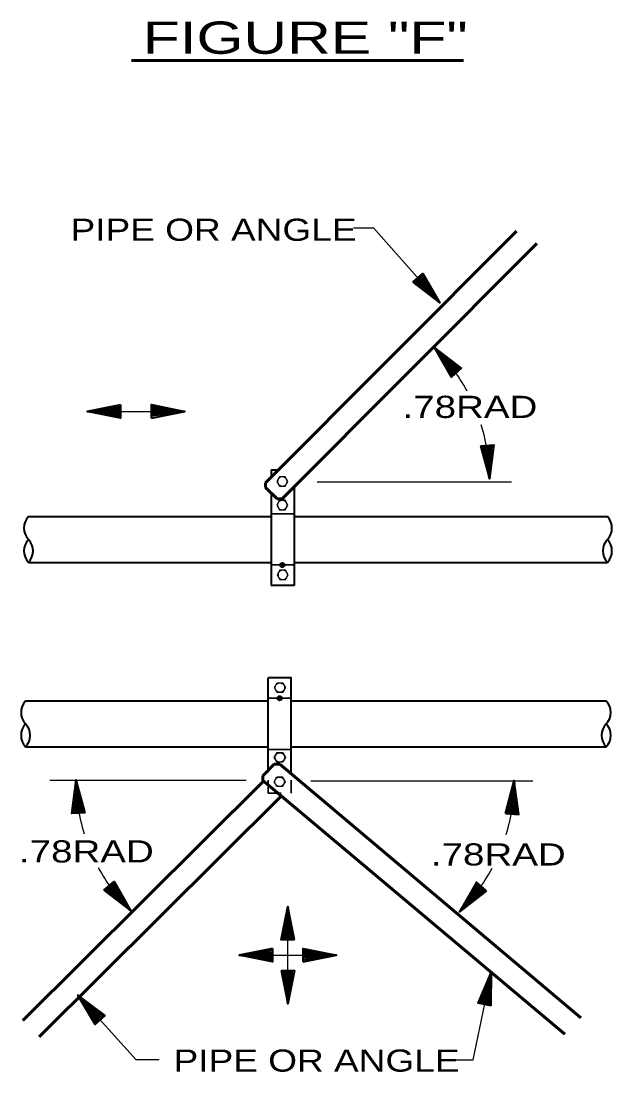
# Model space of a CAD drawing. Extents: x 55 to 190, y 198 to 264.
# Drawn here: x 79.41 to 86.18, y 236.14 to 248.19 of the extents above; entities that cross this region are included whole.
import ezdxf
from ezdxf.enums import TextEntityAlignment as Align

# ---------------------------------------------------------------- set-up
doc = ezdxf.new("R2010")
doc.units = 0
doc.header["$LTSCALE"] = 0.1
doc.header["$PDMODE"] = 32
doc.header["$PDSIZE"] = 0.05
doc.linetypes.add('SHORT_DASHED', pattern=[2.7, 1.5, -1.2])
doc.layers.add('2', color=7, linetype='Continuous', lineweight=40)

msp = doc.modelspace()

# ---------------------------------------------------------------- linework, layer by layer
at = {"layer": '2', "lineweight": 60}
for p, q in [((80.6718, 247.7391), (84.48, 247.7391)), ((82.2109, 242.8975), (85.0859, 245.7806)), ((82.3987, 242.7112), (85.3205, 245.6415)), ((82.2109, 242.8972), (82.2109, 242.8427)), ((82.2109, 242.8427), (82.3429, 242.7112)), ((82.3429, 242.7112), (82.399, 242.7112)), ((82.1784, 239.537), (82.3104, 239.6685)), ((82.3104, 239.6685), (82.3733, 239.6685)), ((82.3733, 239.6685), (85.827, 236.761)), ((82.1868, 239.4756), (79.4264, 236.7303)), ((82.1784, 239.4825), (82.1784, 239.537)), ((82.1784, 239.4825), (85.6415, 236.5734)), ((82.39, 239.3047), (79.6145, 236.544))]:
    msp.add_line(p, q, dxfattribs=at)
at = {"layer": '2'}
for p, q in [((84.2098, 244.9618), (83.9698, 245.2599)), ((84.2098, 244.9618), (83.9976, 245.2848)), ((84.2098, 244.9618), (83.9132, 245.2099)), ((84.2098, 244.9618), (83.9288, 245.2245)), ((84.2098, 244.9618), (83.9421, 245.2353)), ((83.9553, 245.2475), (84.2098, 244.9618)), ((84.3998, 244.1595), (84.1469, 244.4466)), ((84.1469, 244.4466), (84.426, 244.182)), ((84.1469, 244.4466), (84.3572, 244.1225)), ((84.1469, 244.4466), (84.385, 244.1468)), ((84.1469, 244.4466), (84.413, 244.1714)), ((84.1469, 244.4466), (84.4419, 244.1966)), ((80.1654, 243.7158), (80.5477, 243.7727)), ((80.1654, 243.7158), (80.5482, 243.7513)), ((80.1654, 243.7158), (80.5477, 243.7341)), ((80.548, 243.7164), (80.1654, 243.7158)), ((80.1654, 243.7158), (80.5477, 243.6597)), ((80.1654, 243.7158), (80.5477, 243.6971)), ((81.2827, 243.7158), (80.8999, 243.6804)), ((80.9001, 243.7153), (81.2827, 243.7158)), ((81.2827, 243.7158), (80.9004, 243.7719)), ((81.2827, 243.7158), (80.9004, 243.7346)), ((81.2827, 243.7158), (80.9004, 243.6976)), ((81.2827, 243.7158), (80.9004, 243.659)), ((84.7763, 242.9435), (84.8054, 243.3288)), ((84.7763, 242.9435), (84.693, 243.3211)), ((84.7763, 242.9435), (84.7141, 243.3229)), ((84.7763, 242.9435), (84.7311, 243.3237)), ((84.749, 243.325), (84.7763, 242.9435)), ((84.7763, 242.9435), (84.7681, 243.3264)), ((82.2733, 243.0438), (82.2733, 242.9602)), ((82.2733, 243.0438), (82.3606, 243.0438)), ((82.5379, 242.8509), (82.5379, 241.7195)), ((82.2733, 242.7805), (82.2733, 241.7195)), ((79.4912, 242.5117), (82.2733, 242.5117)), ((82.5379, 242.5117), (86.1296, 242.5114)), ((79.4912, 241.9826), (82.2733, 241.9826)), ((82.5379, 241.9826), (86.1296, 241.9823)), ((82.5379, 241.7195), (82.2733, 241.7195)), ((82.2408, 239.5992), (82.2408, 240.6601)), ((82.5056, 240.6601), (82.2408, 240.6601)), ((82.5054, 239.5574), (82.5054, 240.6601)), ((79.4587, 240.3972), (82.2408, 240.3972)), ((82.5054, 240.3972), (86.1164, 240.3972)), ((79.4587, 239.868), (82.2408, 239.868)), ((82.5054, 239.868), (86.1164, 239.868)), ((80.0368, 239.4894), (80.0077, 239.1041)), ((80.0641, 239.1079), (80.0368, 239.4894)), ((80.0368, 239.4894), (80.099, 239.11)), ((80.0368, 239.4894), (80.045, 239.1065)), ((80.0368, 239.4894), (80.0821, 239.1092)), ((80.0368, 239.4894), (80.1202, 239.1118)), ((85.0626, 239.4814), (84.9792, 239.1039)), ((85.0626, 239.4814), (85.0004, 239.102)), ((85.0626, 239.4814), (85.0173, 239.1012)), ((85.0353, 239.0999), (85.0626, 239.4814)), ((85.0626, 239.4814), (85.0544, 239.0986)), ((85.0626, 239.4814), (85.0917, 239.0962)), ((80.4133, 238.2734), (80.6663, 237.9863)), ((80.6663, 237.9863), (80.4281, 238.2861)), ((80.6663, 237.9863), (80.4559, 238.3104)), ((84.4331, 237.9783), (84.6435, 238.3025)), ((84.4331, 237.9783), (84.6713, 238.2781)), ((80.6663, 237.9863), (80.3712, 238.2363)), ((80.6663, 237.9863), (80.3871, 238.2509)), ((80.6663, 237.9863), (80.4001, 238.2614)), ((84.6861, 238.2654), (84.4331, 237.9783)), ((84.4331, 237.9783), (84.6993, 238.2535)), ((84.4331, 237.9783), (84.7123, 238.2429)), ((84.4331, 237.9783), (84.7281, 238.2284)), ((82.4644, 238.0376), (82.4083, 237.6553)), ((82.4644, 238.0376), (82.4456, 237.6553)), ((82.4649, 237.655), (82.4644, 238.0376)), ((82.4644, 238.0376), (82.4998, 237.6547)), ((82.4644, 238.0376), (82.4826, 237.6553)), ((82.4644, 238.0376), (82.5212, 237.6553)), ((81.9058, 237.4788), (82.2882, 237.5357)), ((81.9058, 237.4788), (82.2887, 237.5143)), ((81.9058, 237.4788), (82.2882, 237.4971)), ((82.2884, 237.4793), (81.9058, 237.4788)), ((81.9058, 237.4788), (82.2882, 237.4227)), ((81.9058, 237.4788), (82.2882, 237.46)), ((83.0232, 237.4788), (82.6403, 237.4434)), ((82.6406, 237.4783), (83.0232, 237.4788)), ((83.0232, 237.4788), (82.6408, 237.5349)), ((83.0232, 237.4788), (82.6408, 237.4976)), ((83.0232, 237.4788), (82.6408, 237.4605)), ((83.0232, 237.4788), (82.6408, 237.4219)), ((82.4644, 236.9203), (82.4075, 237.3026)), ((82.4644, 236.9203), (82.4289, 237.3031)), ((82.4644, 236.9203), (82.4461, 237.3026)), ((82.4638, 237.3029), (82.4644, 236.9203)), ((82.4644, 236.9203), (82.5204, 237.3026)), ((82.4644, 236.9203), (82.4832, 237.3026)), ((84.8001, 237.287), (84.6676, 236.924)), ((84.8001, 237.287), (84.7043, 236.9163)), ((84.7228, 236.9121), (84.8001, 237.287)), ((84.8001, 237.287), (84.7406, 236.9089)), ((84.8001, 237.287), (84.757, 236.9049)), ((84.8001, 237.287), (84.7781, 236.901)), ((80.3144, 236.7359), (80.0582, 237.0203)), ((80.0582, 237.0203), (80.3403, 236.7589)), ((80.0582, 237.0203), (80.272, 236.6983)), ((80.0582, 237.0203), (80.2998, 236.7231)), ((80.0582, 237.0203), (80.3273, 236.748)), ((80.0582, 237.0203), (80.3559, 236.7737))]:
    msp.add_line(p, q, dxfattribs=at)
at = {"layer": '2', "lineweight": 25}
for p, q in [((80.1654, 243.7158), (81.2827, 243.7158)), ((82.8012, 242.9091), (85.0287, 242.9091)), ((81.9884, 239.4836), (79.7344, 239.4836)), ((82.7287, 239.478), (85.2764, 239.478)), ((82.4644, 236.9203), (82.4644, 238.0376)), ((81.9058, 237.4788), (83.0232, 237.4788))]:
    msp.add_line(p, q, dxfattribs=at)
at = {"layer": '2', "lineweight": 35}
for p, q in [((82.2736, 242.5405), (82.5387, 242.5405)), ((82.2736, 241.954), (82.5387, 241.954)), ((82.2411, 240.4257), (82.5062, 240.4257)), ((82.2411, 239.8391), (82.5062, 239.8391))]:
    msp.add_line(p, q, dxfattribs=at)
at = {"layer": '2', "linetype": 'SHORT_DASHED', "lineweight": 35}
for p, q in [((82.2408, 239.3359), (82.2408, 239.5992)), ((82.5054, 239.3359), (82.5054, 239.5574)), ((82.2408, 239.3359), (82.5054, 239.3359))]:
    msp.add_line(p, q, dxfattribs=at)
at = {"layer": '2', "lineweight": 25}
for points in [[(83.2195, 245.8187), (83.4481, 245.8187), (84.2098, 244.9618)], [(82.4572, 242.9118), (82.4569, 242.9152), (82.4567, 242.9186), (82.4562, 242.9218), (82.4554, 242.9253), (82.4546, 242.9284), (82.4533, 242.9316), (82.4519, 242.9348), (82.4503, 242.938), (82.4488, 242.9409), (82.4469, 242.9438), (82.4448, 242.9464), (82.4424, 242.9491), (82.44, 242.9515), (82.4374, 242.9536), (82.4347, 242.9557), (82.4318, 242.9575), (82.4289, 242.9594), (82.426, 242.961), (82.4228, 242.9623), (82.4196, 242.9633), (82.4162, 242.9644), (82.413, 242.9652), (82.4096, 242.9657), (82.4062, 242.966), (82.4027, 242.966), (82.3993, 242.966), (82.3958, 242.9657), (82.3927, 242.9652), (82.3892, 242.9644), (82.386, 242.9633), (82.3829, 242.9623), (82.3797, 242.961), (82.3765, 242.9594), (82.3736, 242.9575), (82.3707, 242.9557), (82.3681, 242.9536), (82.3654, 242.9515), (82.363, 242.9491), (82.3609, 242.9464), (82.3588, 242.9438), (82.3569, 242.9409), (82.3551, 242.938), (82.3535, 242.9348), (82.3522, 242.9316), (82.3511, 242.9284), (82.3501, 242.9253), (82.3493, 242.9218), (82.3487, 242.9186), (82.3485, 242.9152), (82.3485, 242.9118), (82.3485, 242.9083), (82.3487, 242.9049), (82.3493, 242.9014), (82.3501, 242.8983), (82.3511, 242.8948), (82.3522, 242.8917), (82.3535, 242.8885), (82.3551, 242.8856), (82.3569, 242.8827), (82.3588, 242.8798), (82.3609, 242.8771), (82.363, 242.8745), (82.3654, 242.8721), (82.3681, 242.8697), (82.3707, 242.8676), (82.3736, 242.8657), (82.3765, 242.8641), (82.3797, 242.8625), (82.3829, 242.8612), (82.386, 242.8599), (82.3892, 242.8591), (82.3927, 242.8583), (82.3958, 242.8578), (82.3993, 242.8575), (82.4027, 242.8573), (82.4062, 242.8575), (82.4096, 242.8578), (82.413, 242.8583), (82.4162, 242.8591), (82.4196, 242.8599), (82.4228, 242.8612), (82.426, 242.8625), (82.4289, 242.8641), (82.4318, 242.8657), (82.4347, 242.8676), (82.4374, 242.8697), (82.44, 242.8721), (82.4424, 242.8745), (82.4448, 242.8771), (82.4469, 242.8798), (82.4488, 242.8827), (82.4503, 242.8856), (82.4519, 242.8885), (82.4533, 242.8917), (82.4546, 242.8948), (82.4554, 242.8983), (82.4562, 242.9014), (82.4567, 242.9049)], [(82.4564, 242.6406), (82.4564, 242.644), (82.4559, 242.6474), (82.4554, 242.6509), (82.4548, 242.6541), (82.4538, 242.6575), (82.4527, 242.6607), (82.4514, 242.6639), (82.4498, 242.6668), (82.448, 242.6697), (82.4461, 242.6726), (82.444, 242.6752), (82.4416, 242.6779), (82.4392, 242.6803), (82.4368, 242.6824), (82.4339, 242.6845), (82.4313, 242.6866), (82.4284, 242.6882), (82.4252, 242.6898), (82.422, 242.6911), (82.4189, 242.6924), (82.4157, 242.6932), (82.4122, 242.694), (82.4088, 242.6945), (82.4054, 242.6948), (82.4022, 242.6951), (82.3987, 242.6948), (82.3953, 242.6945), (82.3919, 242.694), (82.3884, 242.6932), (82.3853, 242.6924), (82.3821, 242.6911), (82.3789, 242.6898), (82.3757, 242.6882), (82.3728, 242.6866), (82.3702, 242.6845), (82.3673, 242.6824), (82.3649, 242.6803), (82.3625, 242.6779), (82.3601, 242.6752), (82.358, 242.6726), (82.3562, 242.6697), (82.3543, 242.6668), (82.3527, 242.6639), (82.3514, 242.6607), (82.3503, 242.6575), (82.3493, 242.6541), (82.3487, 242.6509), (82.3482, 242.6474), (82.3477, 242.644), (82.3477, 242.6406), (82.3477, 242.6371), (82.3482, 242.6337), (82.3487, 242.6303), (82.3493, 242.6271), (82.3503, 242.6236), (82.3514, 242.6205), (82.3527, 242.6173), (82.3543, 242.6144), (82.3562, 242.6115), (82.358, 242.6086), (82.3601, 242.6059), (82.3625, 242.6033), (82.3649, 242.6009), (82.3673, 242.5988), (82.3702, 242.5966), (82.3728, 242.5945), (82.3757, 242.5929), (82.3789, 242.5914), (82.3821, 242.59), (82.3853, 242.5887), (82.3884, 242.5879), (82.3919, 242.5871), (82.3953, 242.5866), (82.3987, 242.5863), (82.4022, 242.5861), (82.4054, 242.5863), (82.4088, 242.5866), (82.4122, 242.5871), (82.4157, 242.5879), (82.4189, 242.5887), (82.422, 242.59), (82.4252, 242.5914), (82.4284, 242.5929), (82.4313, 242.5945), (82.4339, 242.5966), (82.4368, 242.5988), (82.4392, 242.6009), (82.4416, 242.6033), (82.444, 242.6059), (82.4461, 242.6086), (82.448, 242.6115), (82.4498, 242.6144), (82.4514, 242.6173), (82.4527, 242.6205), (82.4538, 242.6236), (82.4548, 242.6271), (82.4554, 242.6303), (82.4559, 242.6337)], [(82.4615, 241.8407), (82.4615, 241.8442), (82.4609, 241.8476), (82.4604, 241.8511), (82.4599, 241.8545), (82.4588, 241.8577), (82.4578, 241.8608), (82.4564, 241.864), (82.4548, 241.8669), (82.453, 241.8701), (82.4511, 241.8727), (82.449, 241.8754), (82.4466, 241.878), (82.4443, 241.8804), (82.4419, 241.8828), (82.439, 241.8849), (82.4363, 241.8868), (82.4334, 241.8886), (82.4302, 241.8899), (82.4271, 241.8915), (82.4239, 241.8926), (82.4207, 241.8936), (82.4173, 241.8942), (82.4138, 241.8947), (82.4104, 241.8952), (82.407, 241.8952), (82.4038, 241.8952), (82.4003, 241.8947), (82.3969, 241.8942), (82.3935, 241.8936), (82.3903, 241.8926), (82.3871, 241.8915), (82.3839, 241.8899), (82.3808, 241.8886), (82.3778, 241.8868), (82.3752, 241.8849), (82.3723, 241.8828), (82.3699, 241.8804), (82.3675, 241.878), (82.3651, 241.8754), (82.363, 241.8727), (82.3612, 241.8701), (82.3593, 241.8669), (82.3577, 241.864), (82.3564, 241.8608), (82.3553, 241.8577), (82.3543, 241.8545), (82.3538, 241.8511), (82.3532, 241.8476), (82.3527, 241.8442), (82.3527, 241.8407), (82.3527, 241.8376), (82.3532, 241.8341), (82.3538, 241.8307), (82.3543, 241.8272), (82.3553, 241.8241), (82.3564, 241.8209), (82.3577, 241.8177), (82.3593, 241.8145), (82.3612, 241.8116), (82.363, 241.809), (82.3651, 241.8061), (82.3675, 241.8037), (82.3699, 241.8013), (82.3723, 241.7989), (82.3752, 241.7968), (82.3778, 241.795), (82.3808, 241.7931), (82.3839, 241.7915), (82.3871, 241.7902), (82.3903, 241.7891), (82.3935, 241.7881), (82.3969, 241.7873), (82.4003, 241.7868), (82.4038, 241.7865), (82.407, 241.7865), (82.4104, 241.7865), (82.4138, 241.7868), (82.4173, 241.7873), (82.4207, 241.7881), (82.4239, 241.7891), (82.4271, 241.7902), (82.4302, 241.7915), (82.4334, 241.7931), (82.4363, 241.795), (82.439, 241.7968), (82.4419, 241.7989), (82.4443, 241.8013), (82.4466, 241.8037), (82.449, 241.8061), (82.4511, 241.809), (82.453, 241.8116), (82.4548, 241.8145), (82.4564, 241.8177), (82.4578, 241.8209), (82.4588, 241.8241), (82.4599, 241.8272), (82.4604, 241.8307), (82.4609, 241.8341)], [(82.4289, 240.5475), (82.4289, 240.544), (82.4286, 240.5406), (82.4281, 240.5371), (82.4273, 240.534), (82.4263, 240.5305), (82.4252, 240.5273), (82.4239, 240.5242), (82.4223, 240.5212), (82.4204, 240.5183), (82.4186, 240.5154), (82.4165, 240.5128), (82.4144, 240.5101), (82.412, 240.5078), (82.4093, 240.5054), (82.4067, 240.5035), (82.4038, 240.5014), (82.4009, 240.4998), (82.3977, 240.4982), (82.3945, 240.4969), (82.3913, 240.4956), (82.3882, 240.4948), (82.3847, 240.494), (82.3816, 240.4935), (82.3781, 240.4932), (82.3747, 240.4929), (82.3712, 240.4932), (82.3678, 240.4935), (82.3643, 240.494), (82.3612, 240.4948), (82.3577, 240.4956), (82.3546, 240.4969), (82.3514, 240.4982), (82.3485, 240.4998), (82.3456, 240.5014), (82.3427, 240.5035), (82.34, 240.5054), (82.3374, 240.5078), (82.335, 240.5101), (82.3326, 240.5128), (82.3305, 240.5154), (82.3286, 240.5183), (82.327, 240.5212), (82.3255, 240.5242), (82.3241, 240.5273), (82.3228, 240.5305), (82.322, 240.534), (82.3212, 240.5371), (82.3207, 240.5406), (82.3204, 240.544), (82.3202, 240.5475), (82.3204, 240.5509), (82.3207, 240.5543), (82.3212, 240.5575), (82.322, 240.5609), (82.3228, 240.5641), (82.3241, 240.5675), (82.3255, 240.5705), (82.327, 240.5736), (82.3286, 240.5765), (82.3305, 240.5795), (82.3326, 240.5821), (82.335, 240.5847), (82.3374, 240.5871), (82.34, 240.5893), (82.3427, 240.5914), (82.3456, 240.5932), (82.3485, 240.5951), (82.3514, 240.5967), (82.3546, 240.598), (82.3577, 240.599), (82.3612, 240.6001), (82.3643, 240.6009), (82.3678, 240.6014), (82.3712, 240.6017), (82.3747, 240.6017), (82.3781, 240.6017), (82.3816, 240.6014), (82.3847, 240.6009), (82.3882, 240.6001), (82.3913, 240.599), (82.3945, 240.598), (82.3977, 240.5967), (82.4009, 240.5951), (82.4038, 240.5932), (82.4067, 240.5914), (82.4093, 240.5893), (82.412, 240.5871), (82.4144, 240.5847), (82.4165, 240.5821), (82.4186, 240.5795), (82.4204, 240.5765), (82.4223, 240.5736), (82.4239, 240.5705), (82.4252, 240.5675), (82.4263, 240.5641), (82.4273, 240.5609), (82.4281, 240.5575), (82.4286, 240.5543)], [(82.4281, 239.7474), (82.4281, 239.7439), (82.4279, 239.7407), (82.4273, 239.7373), (82.4265, 239.7339), (82.4255, 239.7307), (82.4244, 239.7275), (82.4231, 239.7243), (82.4215, 239.7212), (82.4196, 239.7182), (82.4178, 239.7153), (82.4157, 239.7127), (82.4136, 239.7103), (82.4112, 239.7077), (82.4085, 239.7055), (82.4059, 239.7034), (82.403, 239.7016), (82.4001, 239.6997), (82.3969, 239.6981), (82.3937, 239.6968), (82.3905, 239.6958), (82.3874, 239.6947), (82.3839, 239.6939), (82.3808, 239.6934), (82.3773, 239.6931), (82.3739, 239.6931), (82.3704, 239.6931), (82.367, 239.6934), (82.3636, 239.6939), (82.3604, 239.6947), (82.3569, 239.6958), (82.3538, 239.6968), (82.3506, 239.6981), (82.3477, 239.6997), (82.3448, 239.7016), (82.3419, 239.7034), (82.3392, 239.7055), (82.3366, 239.7077), (82.3342, 239.7103), (82.3318, 239.7127), (82.3297, 239.7153), (82.3278, 239.7182), (82.3263, 239.7212), (82.3247, 239.7243), (82.3233, 239.7275), (82.322, 239.7307), (82.3212, 239.7339), (82.3204, 239.7373), (82.3199, 239.7407), (82.3196, 239.7439), (82.3194, 239.7474), (82.3196, 239.7508), (82.3199, 239.7542), (82.3204, 239.7577), (82.3212, 239.7608), (82.322, 239.7643), (82.3233, 239.7675), (82.3247, 239.7706), (82.3263, 239.7735), (82.3278, 239.7765), (82.3297, 239.7794), (82.3318, 239.782), (82.3342, 239.7847), (82.3366, 239.787), (82.3392, 239.7894), (82.3419, 239.7915), (82.3448, 239.7934), (82.3477, 239.795), (82.3506, 239.7966), (82.3538, 239.7979), (82.3569, 239.7992), (82.3604, 239.8), (82.3636, 239.8008), (82.367, 239.8013), (82.3704, 239.8018), (82.3739, 239.8018), (82.3773, 239.8018), (82.3808, 239.8013), (82.3839, 239.8008), (82.3874, 239.8), (82.3905, 239.7992), (82.3937, 239.7979), (82.3969, 239.7966), (82.4001, 239.795), (82.403, 239.7934), (82.4059, 239.7915), (82.4085, 239.7894), (82.4112, 239.787), (82.4136, 239.7847), (82.4157, 239.782), (82.4178, 239.7794), (82.4196, 239.7765), (82.4215, 239.7735), (82.4231, 239.7706), (82.4244, 239.7675), (82.4255, 239.7643), (82.4265, 239.7608), (82.4273, 239.7577), (82.4279, 239.7542)], [(82.4247, 239.4682), (82.4247, 239.4648), (82.4241, 239.4613), (82.4236, 239.4579), (82.4231, 239.4545), (82.422, 239.4513), (82.421, 239.4481), (82.4196, 239.4449), (82.4181, 239.4417), (82.4162, 239.4388), (82.4144, 239.4362), (82.4122, 239.4333), (82.4099, 239.4309), (82.4075, 239.4285), (82.4051, 239.4261), (82.4022, 239.424), (82.3995, 239.4222), (82.3966, 239.4203), (82.3935, 239.4187), (82.3903, 239.4174), (82.3871, 239.4164), (82.3839, 239.4153), (82.3805, 239.4148), (82.3771, 239.4142), (82.3736, 239.4137), (82.3704, 239.4137), (82.367, 239.4137), (82.3636, 239.4142), (82.3601, 239.4148), (82.3567, 239.4153), (82.3535, 239.4164), (82.3503, 239.4174), (82.3472, 239.4187), (82.344, 239.4203), (82.3411, 239.4222), (82.3384, 239.424), (82.3355, 239.4261), (82.3331, 239.4285), (82.3308, 239.4309), (82.3284, 239.4333), (82.3263, 239.4362), (82.3244, 239.4388), (82.3225, 239.4417), (82.321, 239.4449), (82.3196, 239.4481), (82.3186, 239.4513), (82.3175, 239.4545), (82.317, 239.4579), (82.3165, 239.4613), (82.3159, 239.4648), (82.3159, 239.4682), (82.3159, 239.4714), (82.3165, 239.4748), (82.317, 239.4783), (82.3175, 239.4817), (82.3186, 239.4849), (82.3196, 239.488), (82.321, 239.4912), (82.3225, 239.4944), (82.3244, 239.4973), (82.3263, 239.5), (82.3284, 239.5029), (82.3308, 239.5053), (82.3331, 239.5076), (82.3355, 239.51), (82.3384, 239.5121), (82.3411, 239.514), (82.344, 239.5158), (82.3472, 239.5174), (82.3503, 239.5188), (82.3535, 239.5198), (82.3567, 239.5209), (82.3601, 239.5214), (82.3636, 239.5219), (82.367, 239.5225), (82.3704, 239.5225), (82.3736, 239.5225), (82.3771, 239.5219), (82.3805, 239.5214), (82.3839, 239.5209), (82.3871, 239.5198), (82.3903, 239.5188), (82.3935, 239.5174), (82.3966, 239.5158), (82.3995, 239.514), (82.4022, 239.5121), (82.4051, 239.51), (82.4075, 239.5076), (82.4099, 239.5053), (82.4122, 239.5029), (82.4144, 239.5), (82.4162, 239.4973), (82.4181, 239.4944), (82.4196, 239.4912), (82.421, 239.488), (82.422, 239.4849), (82.4231, 239.4817), (82.4236, 239.4783), (82.4241, 239.4748)], [(84.3813, 236.2776), (84.5908, 236.2776), (84.8001, 237.287)], [(80.9914, 236.2776), (80.7247, 236.2776), (80.0582, 237.0203)]]:
    msp.add_lwpolyline(points, dxfattribs=at)
at = {"layer": '2'}
for points in [[(83.8987, 245.197), (84.0132, 245.2983), (84.2098, 244.9618)], [(83.8987, 245.197), (84.2098, 244.9618), (83.9836, 245.2726)], [(84.4564, 244.2093), (84.3411, 244.1087), (84.1469, 244.4466)], [(84.4564, 244.2093), (84.1469, 244.4466), (84.3712, 244.1341)], [(80.5477, 243.792), (80.5475, 243.6391), (80.1654, 243.7158)], [(80.5477, 243.792), (80.1654, 243.7158), (80.548, 243.6783)], [(80.9004, 243.6396), (81.2827, 243.7158), (80.9001, 243.7534)], [(80.9004, 243.6396), (80.9007, 243.7926), (81.2827, 243.7158)], [(84.6734, 243.3195), (84.8263, 243.3303), (84.7763, 242.9435)], [(84.6734, 243.3195), (84.7763, 242.9435), (84.7871, 243.328)], [(80.1397, 239.1134), (79.9868, 239.1026), (80.0368, 239.4894)], [(80.1397, 239.1134), (80.0368, 239.4894), (80.026, 239.1049)], [(84.9597, 239.1055), (85.1126, 239.0946), (85.0626, 239.4814)], [(84.9597, 239.1055), (85.0626, 239.4814), (85.0734, 239.097)], [(80.3567, 238.2236), (80.4721, 238.3242), (80.6663, 237.9863)], [(80.3567, 238.2236), (80.6663, 237.9863), (80.4419, 238.2987)], [(84.7427, 238.2157), (84.6273, 238.3162), (84.4331, 237.9783)], [(84.7427, 238.2157), (84.4331, 237.9783), (84.6575, 238.2908)], [(82.5406, 237.6553), (82.3876, 237.6556), (82.4644, 238.0376)], [(82.5406, 237.6553), (82.4644, 238.0376), (82.4268, 237.655)], [(82.2882, 237.555), (82.2879, 237.4021), (81.9058, 237.4788)], [(82.2882, 237.555), (81.9058, 237.4788), (82.2884, 237.4412)], [(82.6408, 237.4026), (82.6411, 237.5555), (83.0232, 237.4788)], [(82.6408, 237.4026), (83.0232, 237.4788), (82.6406, 237.5164)], [(82.3882, 237.3026), (82.4644, 236.9203), (82.5019, 237.3029)], [(82.3882, 237.3026), (82.5411, 237.3023), (82.4644, 236.9203)], [(84.7972, 236.897), (84.6474, 236.9285), (84.8001, 237.287)], [(84.7972, 236.897), (84.8001, 237.287), (84.6855, 236.92)], [(80.3705, 236.7867), (80.2564, 236.6845), (80.0582, 237.0203)], [(80.3705, 236.7867), (80.0582, 237.0203), (80.2858, 236.7105)]]:
    msp.add_lwpolyline(points, dxfattribs=at)
at = {"layer": '2', "lineweight": 25}
for points in [[(82.4662, 242.9118), (82.4345, 242.9668), (82.371, 242.9668), (82.3392, 242.9118), (82.371, 242.8567), (82.4345, 242.8567)], [(82.4654, 242.6406), (82.4339, 242.6956), (82.3702, 242.6956), (82.3387, 242.6406), (82.3702, 242.5855), (82.4339, 242.5855)], [(82.4705, 241.8407), (82.4387, 241.8958), (82.3752, 241.8958), (82.3435, 241.8407), (82.3752, 241.786), (82.4387, 241.786)], [(82.4382, 240.5475), (82.4064, 240.4924), (82.3429, 240.4924), (82.3112, 240.5475), (82.3429, 240.6025), (82.4064, 240.6025)], [(82.4374, 239.7474), (82.4056, 239.6923), (82.3421, 239.6923), (82.3104, 239.7474), (82.3421, 239.8024), (82.4056, 239.8024)], [(82.4339, 239.4682), (82.4022, 239.4132), (82.3387, 239.4132), (82.3069, 239.4682), (82.3387, 239.523), (82.4022, 239.523)]]:
    msp.add_lwpolyline(points, close=True, dxfattribs=at)
for centre, start, end in [((82.6667, 242.9436), 28.38076, 45.43875), ((82.6667, 242.9436), 0, 17.02996), ((82.1464, 239.4893), 180, 197.02996), ((82.953, 239.4813), 342.97004, 0), ((82.1464, 239.4893), 208.38076, 225.43875), ((82.953, 239.4813), 314.56125, 331.61924)]:
    msp.add_arc(centre, 2.1095, start, end, dxfattribs=at)
at = {"layer": '2'}
for centre, start, end in [((79.6268, 242.3776), 135.97881, 224.0225), ((85.994, 242.3773), 315.9775, 44.02119), ((79.6268, 242.1155), 135.9775, 224.02119), ((79.3556, 242.1155), 315.97881, 44.0225), ((86.2652, 242.1152), 135.9775, 224.02119), ((85.994, 242.1152), 315.97881, 44.0225), ((79.5943, 240.263), 135.97881, 224.0225), ((85.9808, 240.263), 315.9775, 44.02119), ((79.5943, 240.0009), 135.9775, 224.02119), ((79.3231, 240.0009), 315.97881, 44.0225), ((86.252, 240.0009), 135.9775, 224.02119), ((85.9808, 240.0009), 315.97881, 44.0225)]:
    msp.add_arc(centre, 0.1886, start, end, dxfattribs=at)
for p in [(82.403, 241.9537), (82.3707, 240.426)]:
    msp.add_point(p, dxfattribs=at)

# ---------------------------------------------------------------- texts
for s, height, width, p in [('FIGURE "F"', 0.3704, 1.4, (82.6654, 247.8161)), ('.78RAD', 0.254, 1.3, (84.554, 243.6403)), ('.78RAD', 0.254, 1.3, (80.1554, 238.5427)), ('.78RAD', 0.254, 1.3, (84.8791, 238.5078))]:
    msp.add_text(s, height=height, dxfattribs=dict(at, width=width)).set_placement(p, align=Align.CENTER)
at = {"layer": '2', "width": 1.25}
for p in [(83.2531, 245.6716), (84.4345, 236.1437)]:
    msp.add_text('PIPE OR ANGLE', height=0.254, dxfattribs=at).set_placement(p, align=Align.RIGHT)

doc.saveas('drawing.dxf')
